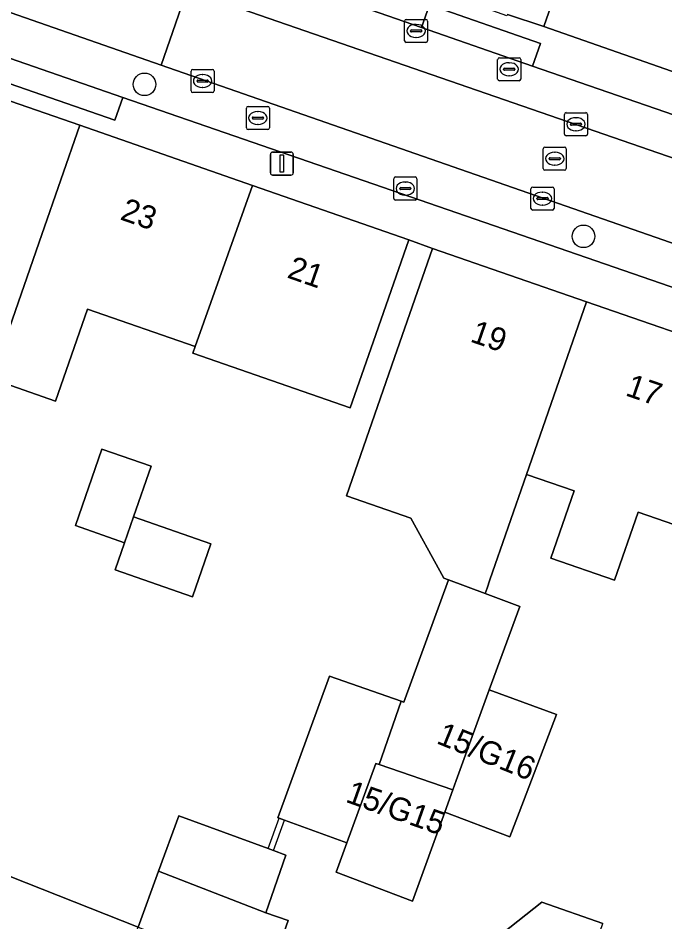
# Model space of a CAD drawing. Extents: x 160023 to 161302, y 384750 to 385707.
# Drawn here: x 160677 to 160705, y 385196.71 to 385235.83 of the extents above; entities that cross this region are included whole.
import ezdxf

# ---------------------------------------------------------------- set-up
doc = ezdxf.new("R2010")
doc.units = 0
for name, color, linetype in [('IMGEO_Boom', 7, 'Continuous'), ('IMGEO_Erf', 7, 'Continuous'), ('IMGEO_Kolk', 7, 'Continuous'), ('IMGEO_Lichtmast', 7, 'Continuous'), ('IMGEO_Muur', 7, 'Continuous'), ('IMGEO_Pand', 7, 'Continuous'), ('IMGEO_Pand_nummerreeks', 7, 'Continuous'), ('IMGEO_Parkeervlak_open', 7, 'Continuous'), ('IMGEO_Rijbaan_lokaal_open', 7, 'Continuous'), ('IMGEO_Rioolput', 7, 'Continuous'), ('IMGEO_Voetpad_open', 7, 'Continuous')]:
    doc.layers.add(name, color=color, linetype=linetype)

msp = doc.modelspace()

# ---------------------------------------------------------------- linework, layer by layer
at = {"layer": 'IMGEO_Boom'}
for centre in [(160682.472, 385232.96), (160701.475, 385226.381)]:
    msp.add_circle(centre, 0.489, dxfattribs=at)
at = {"layer": 'IMGEO_Erf'}
for points in [[(160698.182, 385235.981), (160699.756, 385235.457), (160701.405, 385240.178)], [(160705.799, 385213.767), (160703.837, 385214.447), (160702.813, 385211.494), (160700.058, 385212.449), (160701.066, 385215.359), (160699.009, 385216.072), (160697.428, 385211.51), (160697.305, 385211.154), (160697.224, 385210.921), (160698.717, 385210.367), (160697.398, 385206.749), (160700.314, 385205.686), (160698.881, 385201.936), (160698.29, 385200.388), (160695.472, 385201.465), (160694.067, 385197.61), (160690.776, 385198.863), (160691.236, 385200.126), (160688.53, 385201.113), (160688.299, 385201.197), (160688.243, 385201.217), (160690.476, 385207.343), (160693.583, 385206.266), (160693.697, 385206.224), (160695.625, 385211.515), (160695.429, 385211.588), (160695.256, 385211.9), (160693.998, 385214.182), (160691.221, 385215.144), (160693.298, 385221.137), (160694.935, 385225.861), (160693.912, 385226.232), (160692.269, 385221.51), (160691.381, 385218.959), (160684.571, 385221.329), (160684.67, 385221.61), (160679.999, 385223.235), (160678.613, 385219.254), (160675.853, 385220.214), (160678.029, 385226.466), (160679.672, 385231.188), (160676.673, 385232.236)], [(160675.944, 385198.942), (160682.196, 385196.482), (160683.078, 385198.901), (160683.953, 385201.302), (160687.821, 385199.885), (160688.052, 385199.801), (160688.597, 385199.601), (160687.731, 385197.107), (160688.685, 385196.776), (160687.829, 385194.31)], [(160696.557, 385195.089), (160699.671, 385197.557), (160702.315, 385196.639)]]:
    msp.add_lwpolyline(points, dxfattribs=at)
msp.add_lwpolyline([(160679.479, 385213.86), (160680.629, 385217.167), (160682.757, 385216.427), (160681.994, 385214.234), (160685.339, 385213.07), (160684.543, 385210.783), (160681.198, 385211.948), (160681.606, 385213.12)], close=True, dxfattribs=at)
at = {"layer": 'IMGEO_Kolk'}
for p, q in [((160693.803, 385235.773), (160694.655, 385235.773)), ((160693.728, 385234.847), (160693.728, 385235.699)), ((160694.216, 385235.553), (160694.241, 385235.553)), ((160694.729, 385235.699), (160694.729, 385234.847)), ((160693.987, 385235.267), (160693.987, 385235.279)), ((160694.425, 385235.23), (160694.027, 385235.23)), ((160694.03, 385235.316), (160694.428, 385235.316)), ((160694.239, 385234.993), (160694.214, 385234.993)), ((160694.471, 385235.279), (160694.471, 385235.267)), ((160694.655, 385234.773), (160693.803, 385234.773)), ((160697.76, 385233.188), (160697.76, 385234.04)), ((160697.835, 385234.114), (160698.687, 385234.114)), ((160698.248, 385233.894), (160698.273, 385233.894)), ((160698.761, 385234.04), (160698.761, 385233.188)), ((160684.486, 385232.678), (160684.486, 385233.53)), ((160684.561, 385233.604), (160685.413, 385233.604)), ((160685.487, 385233.53), (160685.487, 385232.678)), ((160698.019, 385233.608), (160698.019, 385233.62)), ((160698.457, 385233.571), (160698.059, 385233.571)), ((160698.062, 385233.657), (160698.46, 385233.657)), ((160698.503, 385233.62), (160698.503, 385233.608)), ((160684.745, 385233.098), (160684.745, 385233.11)), ((160685.183, 385233.061), (160684.785, 385233.061)), ((160684.788, 385233.147), (160685.186, 385233.147)), ((160684.974, 385233.384), (160684.999, 385233.384)), ((160685.229, 385233.11), (160685.229, 385233.098)), ((160698.687, 385233.114), (160697.835, 385233.114)), ((160698.271, 385233.334), (160698.246, 385233.334)), ((160684.997, 385232.824), (160684.972, 385232.824)), ((160685.413, 385232.604), (160684.561, 385232.604)), ((160686.881, 385231.076), (160686.881, 385231.928)), ((160686.956, 385232.002), (160687.808, 385232.002)), ((160687.882, 385231.928), (160687.882, 385231.076)), ((160687.14, 385231.496), (160687.14, 385231.508)), ((160687.183, 385231.545), (160687.581, 385231.545)), ((160687.369, 385231.782), (160687.394, 385231.782)), ((160687.624, 385231.508), (160687.624, 385231.496)), ((160700.65, 385230.808), (160700.65, 385231.66)), ((160700.725, 385231.734), (160701.577, 385231.734)), ((160701.138, 385231.514), (160701.163, 385231.514)), ((160701.651, 385231.66), (160701.651, 385230.808)), ((160687.578, 385231.459), (160687.18, 385231.459)), ((160687.392, 385231.222), (160687.367, 385231.222)), ((160700.909, 385231.228), (160700.909, 385231.24)), ((160701.347, 385231.191), (160700.949, 385231.191)), ((160700.952, 385231.277), (160701.35, 385231.277)), ((160701.393, 385231.24), (160701.393, 385231.228)), ((160687.808, 385231.002), (160686.956, 385231.002)), ((160701.577, 385230.734), (160700.725, 385230.734)), ((160701.161, 385230.954), (160701.136, 385230.954)), ((160693.262, 385228.024), (160693.262, 385228.876)), ((160693.337, 385228.95), (160694.189, 385228.95)), ((160693.75, 385228.73), (160693.775, 385228.73)), ((160694.263, 385228.876), (160694.263, 385228.024)), ((160693.521, 385228.444), (160693.521, 385228.456)), ((160693.959, 385228.407), (160693.561, 385228.407)), ((160693.564, 385228.493), (160693.962, 385228.493)), ((160694.005, 385228.456), (160694.005, 385228.444)), ((160699.201, 385227.589), (160699.201, 385228.441)), ((160699.276, 385228.515), (160700.128, 385228.515)), ((160700.202, 385228.441), (160700.202, 385227.589)), ((160694.189, 385227.95), (160693.337, 385227.95)), ((160693.773, 385228.17), (160693.748, 385228.17)), ((160699.46, 385228.009), (160699.46, 385228.021)), ((160699.898, 385227.972), (160699.5, 385227.972)), ((160699.503, 385228.058), (160699.901, 385228.058)), ((160699.689, 385228.295), (160699.714, 385228.295)), ((160699.944, 385228.021), (160699.944, 385228.009)), ((160699.712, 385227.735), (160699.687, 385227.735)), ((160700.128, 385227.515), (160699.276, 385227.515))]:
    msp.add_line(p, q, dxfattribs=at)
for points in [[(160693.803, 385235.773), (160694.655, 385235.773)], [(160693.728, 385234.847), (160693.728, 385235.699)], [(160694.729, 385235.699), (160694.729, 385234.847)], [(160694.655, 385234.773), (160693.803, 385234.773)], [(160697.76, 385233.188), (160697.76, 385234.04)], [(160697.835, 385234.114), (160698.687, 385234.114)], [(160698.761, 385234.04), (160698.761, 385233.188)], [(160684.486, 385232.678), (160684.486, 385233.53)], [(160684.561, 385233.604), (160685.413, 385233.604)], [(160685.487, 385233.53), (160685.487, 385232.678)], [(160698.687, 385233.114), (160697.835, 385233.114)], [(160685.413, 385232.604), (160684.561, 385232.604)], [(160686.881, 385231.076), (160686.881, 385231.928)], [(160686.956, 385232.002), (160687.808, 385232.002)], [(160687.882, 385231.928), (160687.882, 385231.076)], [(160700.65, 385230.808), (160700.65, 385231.66)], [(160700.725, 385231.734), (160701.577, 385231.734)], [(160701.651, 385231.66), (160701.651, 385230.808)], [(160687.808, 385231.002), (160686.956, 385231.002)], [(160701.577, 385230.734), (160700.725, 385230.734)], [(160693.262, 385228.024), (160693.262, 385228.876)], [(160693.337, 385228.95), (160694.189, 385228.95)], [(160694.263, 385228.876), (160694.263, 385228.024)], [(160699.201, 385227.589), (160699.201, 385228.441)], [(160699.276, 385228.515), (160700.128, 385228.515)], [(160700.202, 385228.441), (160700.202, 385227.589)], [(160694.189, 385227.95), (160693.337, 385227.95)], [(160700.128, 385227.515), (160699.276, 385227.515)]]:
    msp.add_lwpolyline(points, dxfattribs=at)
for centre, radius, start, end in [((160693.805, 385235.697), 0.0765, 91.552, 178.448), ((160693.805, 385235.697), 0.0765, 91.552, 178.448), ((160694.653, 385235.697), 0.0765, 1.552, 88.448), ((160694.653, 385235.697), 0.0765, 1.552, 88.448), ((160694.027, 385235.276), 0.0403, 85.8775, 175.7526), ((160694.024, 385235.266), 0.0366, 178.938, 274.7102), ((160694.428, 385235.273), 0.043, 264.8664, 352.4533), ((160694.432, 385235.278), 0.0386, 1.7309, 96.639), ((160693.805, 385234.849), 0.0765, 181.552, 268.448), ((160693.805, 385234.849), 0.0765, 181.552, 268.448), ((160694.653, 385234.849), 0.0765, 271.552, 358.448), ((160694.653, 385234.849), 0.0765, 271.552, 358.448), ((160697.837, 385234.038), 0.0765, 91.552, 178.448), ((160697.837, 385234.038), 0.0765, 91.552, 178.448), ((160698.685, 385234.038), 0.0765, 1.552, 88.448), ((160698.685, 385234.038), 0.0765, 1.552, 88.448), ((160684.563, 385233.528), 0.0765, 91.552, 178.448), ((160684.563, 385233.528), 0.0765, 91.552, 178.448), ((160685.411, 385233.528), 0.0765, 1.552, 88.448), ((160685.411, 385233.528), 0.0765, 1.552, 88.448), ((160698.059, 385233.617), 0.0403, 85.8775, 175.7526), ((160698.056, 385233.607), 0.0366, 178.938, 274.7102), ((160698.46, 385233.614), 0.043, 264.8664, 352.4533), ((160698.464, 385233.619), 0.0386, 1.7309, 96.639), ((160684.785, 385233.107), 0.0403, 85.8775, 175.7526), ((160684.782, 385233.097), 0.0366, 178.938, 274.7102), ((160685.186, 385233.104), 0.043, 264.8664, 352.4533), ((160685.19, 385233.109), 0.0386, 1.7309, 96.639), ((160697.837, 385233.19), 0.0765, 181.552, 268.448), ((160697.837, 385233.19), 0.0765, 181.552, 268.448), ((160698.685, 385233.19), 0.0765, 271.552, 358.448), ((160698.685, 385233.19), 0.0765, 271.552, 358.448), ((160684.563, 385232.68), 0.0765, 181.552, 268.448), ((160684.563, 385232.68), 0.0765, 181.552, 268.448), ((160685.411, 385232.68), 0.0765, 271.552, 358.448), ((160685.411, 385232.68), 0.0765, 271.552, 358.448), ((160686.958, 385231.926), 0.0765, 91.552, 178.448), ((160686.958, 385231.926), 0.0765, 91.552, 178.448), ((160687.806, 385231.926), 0.0765, 1.552, 88.448), ((160687.806, 385231.926), 0.0765, 1.552, 88.448), ((160687.18, 385231.505), 0.0403, 85.8775, 175.7526), ((160687.177, 385231.495), 0.0366, 178.938, 274.7102), ((160687.581, 385231.502), 0.043, 264.8664, 352.4533), ((160687.585, 385231.507), 0.0386, 1.7309, 96.639), ((160700.727, 385231.658), 0.0765, 91.552, 178.448), ((160700.727, 385231.658), 0.0765, 91.552, 178.448), ((160701.575, 385231.658), 0.0765, 1.552, 88.448), ((160701.575, 385231.658), 0.0765, 1.552, 88.448), ((160686.958, 385231.078), 0.0765, 181.552, 268.448), ((160686.958, 385231.078), 0.0765, 181.552, 268.448), ((160687.806, 385231.078), 0.0765, 271.552, 358.448), ((160687.806, 385231.078), 0.0765, 271.552, 358.448), ((160700.949, 385231.237), 0.0403, 85.8775, 175.7526), ((160700.946, 385231.227), 0.0366, 178.938, 274.7102), ((160701.35, 385231.234), 0.043, 264.8664, 352.4533), ((160701.354, 385231.239), 0.0386, 1.7309, 96.639), ((160700.727, 385230.81), 0.0765, 181.552, 268.448), ((160700.727, 385230.81), 0.0765, 181.552, 268.448), ((160701.575, 385230.81), 0.0765, 271.552, 358.448), ((160701.575, 385230.81), 0.0765, 271.552, 358.448), ((160693.339, 385228.874), 0.0765, 91.552, 178.448), ((160693.339, 385228.874), 0.0765, 91.552, 178.448), ((160694.187, 385228.874), 0.0765, 1.552, 88.448), ((160694.187, 385228.874), 0.0765, 1.552, 88.448), ((160693.561, 385228.453), 0.0403, 85.8775, 175.7526), ((160693.558, 385228.443), 0.0366, 178.938, 274.7102), ((160693.962, 385228.45), 0.043, 264.8664, 352.4533), ((160693.966, 385228.455), 0.0386, 1.7309, 96.639), ((160699.278, 385228.439), 0.0765, 91.552, 178.448), ((160699.278, 385228.439), 0.0765, 91.552, 178.448), ((160700.126, 385228.439), 0.0765, 1.552, 88.448), ((160700.126, 385228.439), 0.0765, 1.552, 88.448), ((160693.339, 385228.026), 0.0765, 181.552, 268.448), ((160693.339, 385228.026), 0.0765, 181.552, 268.448), ((160694.187, 385228.026), 0.0765, 271.552, 358.448), ((160694.187, 385228.026), 0.0765, 271.552, 358.448), ((160699.5, 385228.018), 0.0403, 85.8775, 175.7526), ((160699.497, 385228.008), 0.0366, 178.938, 274.7102), ((160699.901, 385228.015), 0.043, 264.8664, 352.4533), ((160699.905, 385228.02), 0.0386, 1.7309, 96.639), ((160699.278, 385227.591), 0.0765, 181.552, 268.448), ((160699.278, 385227.591), 0.0765, 181.552, 268.448), ((160700.126, 385227.591), 0.0765, 271.552, 358.448), ((160700.126, 385227.591), 0.0765, 271.552, 358.448)]:
    msp.add_arc(centre, radius, start, end, dxfattribs=at)
for centre, major_axis, ratio, start_param, end_param in [((160694.215, 385235.273), (-0.387, 0.002), 0.722429, 4.712389, 7.853982), ((160694.24, 385235.273), (-0.39, 0.002), 0.717154, 1.570796, 4.712389), ((160698.247, 385233.614), (-0.387, 0.002), 0.722429, 4.712389, 7.853982), ((160698.272, 385233.614), (-0.39, 0.002), 0.717154, 1.570796, 4.712389), ((160684.973, 385233.104), (-0.387, 0.002), 0.722429, 4.712389, 7.853982), ((160684.998, 385233.104), (-0.39, 0.002), 0.717154, 1.570796, 4.712389), ((160687.368, 385231.502), (-0.387, 0.002), 0.722429, 4.712389, 7.853982), ((160687.393, 385231.502), (-0.39, 0.002), 0.717154, 1.570796, 4.712389), ((160701.137, 385231.234), (-0.387, 0.002), 0.722429, 4.712389, 7.853982), ((160701.162, 385231.234), (-0.39, 0.002), 0.717154, 1.570796, 4.712389), ((160693.749, 385228.45), (-0.387, 0.002), 0.722429, 4.712389, 7.853982), ((160693.774, 385228.45), (-0.39, 0.002), 0.717154, 1.570796, 4.712389), ((160699.688, 385228.015), (-0.387, 0.002), 0.722429, 4.712389, 7.853982), ((160699.713, 385228.015), (-0.39, 0.002), 0.717154, 1.570796, 4.712389)]:
    msp.add_ellipse(centre, major_axis=major_axis, ratio=ratio, start_param=start_param, end_param=end_param, dxfattribs=at)
at = {"layer": 'IMGEO_Lichtmast'}
for p, q in [((160687.92, 385229.129), (160687.92, 385229.929)), ((160687.92, 385229.929), (160687.92, 385229.129)), ((160688.02, 385230.029), (160688.81, 385230.029)), ((160688.81, 385230.029), (160688.02, 385230.029)), ((160688.91, 385229.929), (160688.91, 385229.129)), ((160688.91, 385229.129), (160688.91, 385229.929)), ((160688.81, 385229.029), (160688.02, 385229.029)), ((160688.02, 385229.029), (160688.81, 385229.029))]:
    msp.add_line(p, q, dxfattribs=at)
msp.add_lwpolyline([(160688.34, 385229.904), (160688.49, 385229.904), (160688.49, 385229.154), (160688.34, 385229.154), (160688.34, 385229.904)], dxfattribs=at)
for centre, start, end in [((160688.02, 385229.929), 90, 180), ((160688.02, 385229.929), 90, 180), ((160688.81, 385229.929), 0, 90), ((160688.81, 385229.929), 360, 90), ((160688.02, 385229.129), 180, 270), ((160688.02, 385229.129), 180, 270), ((160688.81, 385229.129), 270, 0), ((160688.81, 385229.129), 270, 0)]:
    msp.add_arc(centre, 0.1, start, end, dxfattribs=at)
at = {"layer": 'IMGEO_Muur'}
for points in [[(160687.821, 385199.885), (160688.299, 385201.197)], [(160688.052, 385199.801), (160688.53, 385201.113)]]:
    msp.add_lwpolyline(points, dxfattribs=at)
at = {"layer": 'IMGEO_Pand'}
for points in [[(160712.659, 385250), (160712.914, 385250.729), (160711.302, 385251.313), (160710.843, 385250), (160708.837, 385244.259), (160708.672, 385243.786), (160706.942, 385244.39), (160706.063, 385241.874), (160702.44, 385243.14), (160701.405, 385240.178), (160699.756, 385235.457), (160706.731, 385233.02)], [(160687.144, 385228.588), (160679.672, 385231.188), (160678.029, 385226.466), (160675.853, 385220.214), (160678.613, 385219.254), (160679.999, 385223.235), (160684.67, 385221.61)], [(160693.912, 385226.232), (160687.144, 385228.588), (160684.67, 385221.61), (160684.571, 385221.329), (160691.381, 385218.959), (160692.269, 385221.51)], [(160701.601, 385223.551), (160694.935, 385225.861), (160693.298, 385221.137), (160691.221, 385215.144), (160693.998, 385214.182), (160695.256, 385211.9), (160695.429, 385211.588), (160695.625, 385211.515), (160697.224, 385210.921), (160697.305, 385211.154), (160697.428, 385211.51), (160699.009, 385216.072)], [(160701.601, 385223.551), (160699.009, 385216.072), (160701.066, 385215.359), (160700.058, 385212.449), (160702.813, 385211.494), (160703.837, 385214.447), (160705.799, 385213.767), (160706.739, 385216.479), (160708.376, 385221.203)], [(160681.606, 385213.12), (160681.994, 385214.234), (160682.757, 385216.427), (160680.629, 385217.167), (160679.479, 385213.86)], [(160681.994, 385214.234), (160681.606, 385213.12), (160681.198, 385211.948), (160684.543, 385210.783), (160685.339, 385213.07)], [(160698.717, 385210.367), (160697.224, 385210.921), (160695.625, 385211.515), (160693.697, 385206.224), (160693.583, 385206.266), (160692.63, 385203.518), (160695.821, 385202.422), (160695.97, 385202.832), (160697.398, 385206.749)], [(160693.583, 385206.266), (160690.476, 385207.343), (160688.243, 385201.217), (160688.299, 385201.197), (160688.53, 385201.113), (160691.236, 385200.126), (160692.49, 385203.566), (160692.63, 385203.518)], [(160695.821, 385202.422), (160695.472, 385201.465), (160698.29, 385200.388), (160698.881, 385201.936), (160700.314, 385205.686), (160697.398, 385206.749), (160695.97, 385202.832)], [(160695.821, 385202.422), (160692.63, 385203.518), (160692.49, 385203.566), (160691.236, 385200.126), (160690.776, 385198.863), (160694.067, 385197.61), (160695.472, 385201.465)], [(160688.597, 385199.601), (160688.052, 385199.801), (160687.821, 385199.885), (160683.953, 385201.302), (160683.078, 385198.901), (160687.731, 385197.107)], [(160680.157, 385191.384), (160681.137, 385193.87), (160681.355, 385194.422), (160682.196, 385196.482), (160675.944, 385198.942), (160675.14, 385197.014), (160671.591, 385188.101), (160677.78, 385185.358), (160678.196, 385186.412), (160679.176, 385188.898)], [(160688.685, 385196.776), (160687.731, 385197.107), (160683.078, 385198.901), (160682.196, 385196.482), (160687.829, 385194.31)], [(160700.036, 385190.073), (160702.315, 385196.639), (160699.671, 385197.557), (160696.557, 385195.089), (160695.377, 385191.69)]]:
    msp.add_lwpolyline(points, close=True, dxfattribs=at)
at = {"layer": 'IMGEO_Parkeervlak_open'}
for points in [[(160782.993, 385203.324), (160783.445, 385204.608), (160727.342, 385224.065), (160721.742, 385226.004), (160720.554, 385226.4), (160699.267, 385233.748), (160694.461, 385235.418), (160659.461, 385247.549), (160654.681, 385249.21), (160652.403, 385250), (160639.062, 385254.626), (160635.293, 385255.965)], [(160633.875, 385254.519), (160646.927, 385250), (160676.865, 385239.636), (160684.321, 385237.055), (160720.019, 385224.698), (160728.965, 385221.591), (160783.288, 385202.713)], [(160782.111, 385199.477), (160727.822, 385218.288), (160718.874, 385221.388), (160708.479, 385224.99), (160683.191, 385233.789), (160675.739, 385236.382), (160651.054, 385244.971), (160636.407, 385250), (160632.14, 385251.465)], [(160630.881, 385250), (160631.668, 385249.714), (160639.654, 385246.93), (160644.488, 385245.245), (160659.581, 385239.998), (160663.384, 385238.688), (160676.625, 385234.092), (160681.528, 385232.39), (160708.023, 385223.237), (160712.287, 385221.77), (160781.115, 385197.893), (160781.566, 385199.169)]]:
    msp.add_lwpolyline(points, dxfattribs=at)
at = {"layer": 'IMGEO_Rijbaan_lokaal_open'}
for points in [[(160676.865, 385239.636), (160675.739, 385236.382), (160683.191, 385233.789), (160684.321, 385237.055)], [(160684.321, 385237.055), (160683.191, 385233.789), (160708.479, 385224.99), (160718.874, 385221.388), (160720.019, 385224.698)]]:
    msp.add_lwpolyline(points, close=True, dxfattribs=at)
at = {"layer": 'IMGEO_Rioolput'}
for p, q in [((160699.731, 385229.316), (160699.731, 385230.168)), ((160699.806, 385230.242), (160700.658, 385230.242)), ((160700.219, 385230.022), (160700.244, 385230.022)), ((160700.732, 385230.168), (160700.732, 385229.316)), ((160699.99, 385229.736), (160699.99, 385229.748)), ((160700.428, 385229.699), (160700.03, 385229.699)), ((160700.033, 385229.785), (160700.431, 385229.785)), ((160700.474, 385229.748), (160700.474, 385229.736)), ((160700.658, 385229.242), (160699.806, 385229.242)), ((160700.242, 385229.462), (160700.217, 385229.462))]:
    msp.add_line(p, q, dxfattribs=at)
for points in [[(160699.731, 385229.316), (160699.731, 385230.168)], [(160699.806, 385230.242), (160700.658, 385230.242)], [(160700.732, 385230.168), (160700.732, 385229.316)], [(160700.658, 385229.242), (160699.806, 385229.242)]]:
    msp.add_lwpolyline(points, dxfattribs=at)
for centre, radius, start, end in [((160699.808, 385230.166), 0.0765, 91.552, 178.448), ((160699.808, 385230.166), 0.0765, 91.552, 178.448), ((160700.656, 385230.166), 0.0765, 1.552, 88.448), ((160700.656, 385230.166), 0.0765, 1.552, 88.448), ((160700.03, 385229.745), 0.0403, 85.8775, 175.7526), ((160700.027, 385229.735), 0.0366, 178.938, 274.7102), ((160700.431, 385229.742), 0.043, 264.8664, 352.4533), ((160700.435, 385229.747), 0.0386, 1.7309, 96.639), ((160699.808, 385229.318), 0.0765, 181.552, 268.448), ((160699.808, 385229.318), 0.0765, 181.552, 268.448), ((160700.656, 385229.318), 0.0765, 271.552, 358.448), ((160700.656, 385229.318), 0.0765, 271.552, 358.448)]:
    msp.add_arc(centre, radius, start, end, dxfattribs=at)
for centre, major_axis, ratio, start_param, end_param in [((160700.218, 385229.742), (-0.387, 0.002), 0.722429, 4.712389, 7.853982), ((160700.243, 385229.742), (-0.39, 0.002), 0.717154, 1.570796, 4.712389)]:
    msp.add_ellipse(centre, major_axis=major_axis, ratio=ratio, start_param=start_param, end_param=end_param, dxfattribs=at)
at = {"layer": 'IMGEO_Voetpad_open'}
for points in [[(160635.293, 385255.965), (160639.062, 385254.626), (160652.403, 385250), (160654.681, 385249.21), (160655.023, 385250.193), (160659.803, 385248.532), (160659.461, 385247.549), (160694.461, 385235.418), (160694.803, 385236.401), (160699.612, 385234.731), (160699.267, 385233.748), (160720.554, 385226.4), (160721.742, 385226.004), (160722.083, 385226.987), (160727.687, 385225.047), (160727.342, 385224.065), (160783.445, 385204.608), (160782.993, 385203.324)], [(160712.287, 385221.77), (160711.949, 385220.787), (160707.685, 385222.255), (160708.023, 385223.237), (160681.528, 385232.39), (160681.187, 385231.408), (160676.284, 385233.11), (160676.625, 385234.092), (160663.384, 385238.688), (160663.046, 385237.705), (160659.246, 385239.015), (160659.581, 385239.998), (160644.488, 385245.245), (160644.146, 385244.263), (160639.312, 385245.949), (160639.654, 385246.93), (160631.668, 385249.714), (160630.881, 385250)], [(160739.574, 385221.466), (160738.63, 385221.796), (160733.389, 385223.624), (160732.445, 385223.954), (160723.362, 385227.123), (160721.56, 385227.84), (160713.951, 385230.498), (160706.731, 385233.02), (160699.756, 385235.457), (160698.182, 385235.981), (160698.163, 385235.929), (160696.056, 385236.688), (160688.96, 385239.243), (160687.103, 385239.912), (160680.582, 385242.281), (160673.97, 385244.687)], [(160676.673, 385232.236), (160679.672, 385231.188), (160687.144, 385228.588), (160693.912, 385226.232), (160694.935, 385225.861), (160701.601, 385223.551), (160708.376, 385221.203), (160710.983, 385220.315), (160719.436, 385217.415), (160720.368, 385217.087), (160726.118, 385215.091), (160731.327, 385213.282), (160732.413, 385212.906), (160737.489, 385211.142), (160738.537, 385210.778), (160745.428, 385208.364)]]:
    msp.add_lwpolyline(points, dxfattribs=at)
for points in [[(160694.461, 385235.418), (160699.267, 385233.748), (160699.612, 385234.731), (160694.803, 385236.401)], [(160676.625, 385234.092), (160676.284, 385233.11), (160681.187, 385231.408), (160681.528, 385232.39)]]:
    msp.add_lwpolyline(points, close=True, dxfattribs=at)

# ---------------------------------------------------------------- texts
at = {"layer": 'IMGEO_Pand_nummerreeks'}
for s, rotation, p in [('23', 340.8116, (160681.374, 385227.123)), ('21', 340.8116, (160688.601, 385224.608)), ('19', 340.8861, (160696.527, 385221.837)), ('17', 340.8862, (160703.246, 385219.508)), ('15/G16', 337.9996, (160695.066, 385204.453)), ('15/G15', 340.4892, (160691.133, 385201.915))]:
    msp.add_text(s, height=1, rotation=rotation, dxfattribs=at).set_placement(p)

doc.saveas('drawing.dxf')
